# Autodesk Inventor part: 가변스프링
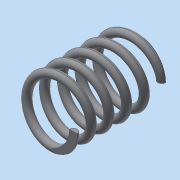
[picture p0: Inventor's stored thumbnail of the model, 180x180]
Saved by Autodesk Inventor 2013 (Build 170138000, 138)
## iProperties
Created: 2019-10
Part Number: 가변스프링
Material: 일반
Document SubType Name: Modeling
Designer: dgall
Density: 1 g/cm^3
Mass: 18.3745 g
Surface Area: 124.173 cm^2
Volume: 18.3745 cm^3
Author: dgall
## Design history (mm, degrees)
sketch "스케치1"
  geometry: L1 (0, 0)-(21, 0); L2 (0, 0)-(0, 67.25); L3 (0, 67.25)-(21, 67.25); C1 r 3 at (21, 0)
  constraints: 6 end point, 2 horizontal, 1 centre point, 1 coincident, 1 perpendicular, 1 vertical alignment
  dimensions: "d0" = 42 diameter of L3.end L2; "d2" = 67.25 distance of L1.start L2.end (derived); "d3" = 6 diameter of C1
feature "코일1" sketch "스케치1" pitch "d4" = 10; turns "d6" = 5; dims "d5" = 67.25 (= d2), "d7" = 0, angle "d8" = 90 deg, angle "d9" = 90 deg, "d10" = 0, "d11" = 0
feature "분할1"
node "작업 평면1"
feature "분할2"
node "솔리드1"
other parameters: "d12" = 0
